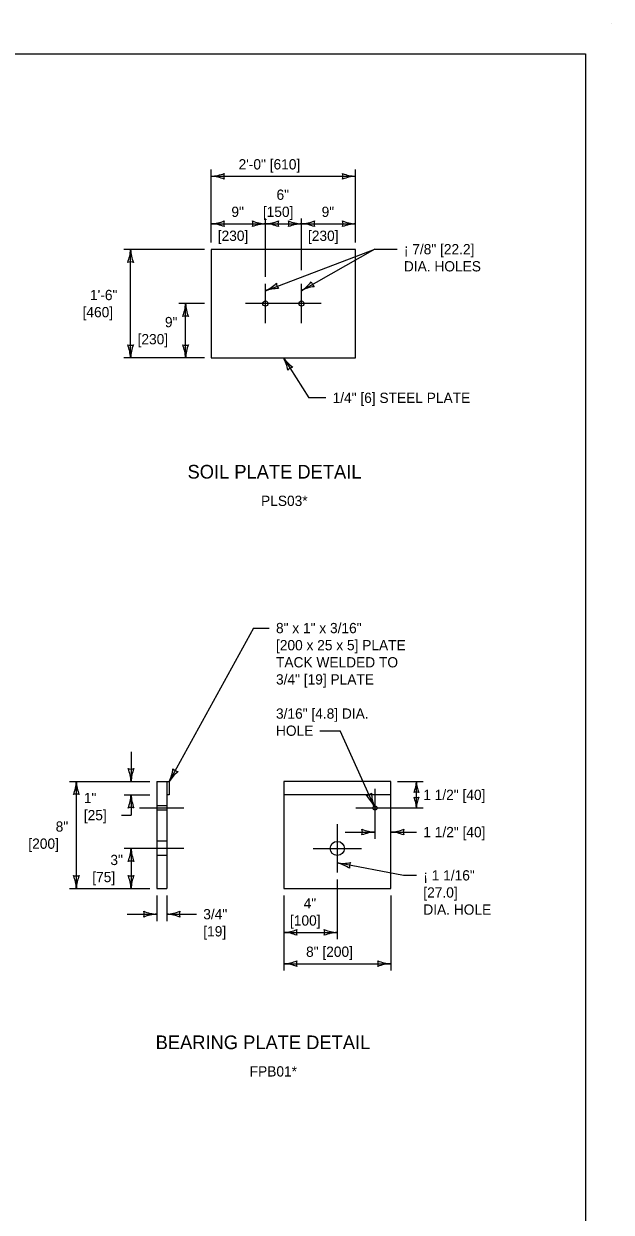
# Model space of a CAD drawing. Extents: x 49991.4 to 50021, y 49987.6 to 50011.4.
# Drawn here: x 50013.47 to 50016.9, y 49992.23 to 49999.18 of the extents above; entities that cross this region are included whole.
import ezdxf

# ---------------------------------------------------------------- set-up
doc = ezdxf.new("R2010")
doc.units = 0
for name, color, linetype in [('Level 1', 7, 'Continuous'), ('Level 2', 7, 'Continuous'), ('Level 3', 7, 'Continuous'), ('Level 4', 7, 'Continuous'), ('Level 5', 7, 'Continuous')]:
    doc.layers.add(name, color=color, linetype=linetype)

msp = doc.modelspace()

# ---------------------------------------------------------------- linework, layer by layer
at = {"layer": 'Level 1'}
for p, q in [((50016.9001, 49999.1756), (50016.9001, 49999.1756)), ((50015.406, 49997.8562), (50014.5622, 49997.8562)), ((50014.5622, 49997.8562), (50014.5622, 49997.2232)), ((50015.406, 49997.2232), (50015.406, 49997.8562)), ((50014.5622, 49997.2232), (50015.406, 49997.2232)), ((50014.2436, 49994.7447), (50014.2436, 49994.1196)), ((50014.2436, 49994.7447), (50014.3169, 49994.7447)), ((50014.3023, 49994.7447), (50014.3023, 49994.1196)), ((50014.3169, 49994.7447), (50014.3169, 49994.6666)), ((50015.6115, 49994.7447), (50014.9865, 49994.7447)), ((50014.9865, 49994.7447), (50014.9865, 49994.1196)), ((50015.6115, 49994.1196), (50015.6115, 49994.7447)), ((50014.3169, 49994.6666), (50014.3023, 49994.6666)), ((50014.2436, 49994.1196), (50014.3023, 49994.1196)), ((50014.9865, 49994.1196), (50015.6115, 49994.1196))]:
    msp.add_line(p, q, dxfattribs=at)
msp.add_lwpolyline([(49999.3835, 49998.9992), (50016.7501, 49998.9992), (50016.7501, 49987.7988), (49999.3835, 49987.7988)], close=True, dxfattribs=at)
for centre, radius in [((50014.8787, 49997.5397), 0.0154), ((50015.0896, 49997.5397), 0.0154), ((50015.2989, 49994.354), 0.0415)]:
    msp.add_circle(centre, radius, dxfattribs=at)
at = {"layer": 'Level 3'}
for p, q in [((50014.5622, 49997.8962), (50014.5622, 49998.3239)), ((50014.5622, 49998.2839), (50015.406, 49998.2839)), ((50015.406, 49997.8962), (50015.406, 49998.3239)), ((50014.5622, 49998.0062), (50014.8787, 49998.0062)), ((50014.8787, 49997.6951), (50014.8787, 49998.0374)), ((50014.8787, 49998.0062), (50015.0896, 49998.0062)), ((50015.0896, 49997.7351), (50015.0896, 49998.0374)), ((50015.0896, 49998.0062), (50015.406, 49998.0062)), ((50014.5222, 49997.8562), (50014.0507, 49997.8562)), ((50014.0907, 49997.2232), (50014.0907, 49997.8562)), ((50014.8787, 49997.6151), (50015.5181, 49997.8576)), ((50015.5181, 49997.8576), (50015.0896, 49997.6151)), ((50015.5181, 49997.8576), (50015.6483, 49997.8576)), ((50014.5222, 49997.5397), (50014.3722, 49997.5397)), ((50014.4122, 49997.2232), (50014.4122, 49997.5397)), ((50014.5222, 49997.2232), (50014.0507, 49997.2232)), ((50014.9841, 49997.2232), (50015.1329, 49996.9886)), ((50015.2316, 49996.9886), (50015.1329, 49996.9886)), ((50014.8092, 49995.6425), (50014.3169, 49994.7447)), ((50014.8092, 49995.6425), (50014.9008, 49995.6425)), ((50015.1976, 49995.0425), (50015.3153, 49995.0425)), ((50015.5142, 49994.6016), (50015.3153, 49995.0425)), ((50014.0936, 49994.9181), (50014.0936, 49994.7447)), ((50013.7337, 49994.7447), (50014.2036, 49994.7447)), ((50013.7737, 49994.7447), (50013.7737, 49994.1196)), ((50015.6515, 49994.7446), (50015.8015, 49994.7446)), ((50015.7615, 49994.5904), (50015.7615, 49994.7446)), ((50014.0536, 49994.6666), (50014.2036, 49994.6666)), ((50014.0936, 49994.6666), (50014.0936, 49994.5488)), ((50014.0373, 49994.5488), (50014.0936, 49994.5488)), ((50015.3458, 49994.4497), (50015.5193, 49994.4497)), ((50015.6115, 49994.4497), (50015.7619, 49994.4497)), ((50014.0936, 49994.354), (50014.0936, 49994.1196)), ((50015.6861, 49994.1967), (50015.2989, 49994.269)), ((50015.2989, 49994.1725), (50015.2989, 49993.8229)), ((50015.7619, 49994.1967), (50015.6861, 49994.1967)), ((50013.7337, 49994.1196), (50014.2036, 49994.1196)), ((50014.2436, 49994.0796), (50014.2436, 49993.9296)), ((50014.3023, 49994.0796), (50014.3023, 49993.9296)), ((50014.9865, 49994.0796), (50014.9865, 49993.6402)), ((50015.6115, 49994.0796), (50015.6115, 49993.6402)), ((50014.0701, 49993.9696), (50014.2436, 49993.9696)), ((50014.3023, 49993.9696), (50014.4757, 49993.9696)), ((50014.9865, 49993.8629), (50015.2989, 49993.8629)), ((50014.9865, 49993.6802), (50015.6115, 49993.6802))]:
    msp.add_line(p, q, dxfattribs=at)
msp.add_circle((50015.5193, 49994.5904), 0.0124, dxfattribs=at)
for centre, radius, start, end in [((50014.5507, 49998.5166), 0.233, 272.82731, 292.07716), ((50014.553, 49998.0617), 0.2223, 67.45601, 87.63952), ((50014.6904, 49998.2839), 0.0548, 162.13882, 197.86118), ((50015.4151, 49998.506), 0.2223, 247.45601, 267.63952), ((50015.2778, 49998.2839), 0.0548, 342.13882, 17.86118), ((50015.4175, 49998.0511), 0.233, 92.82731, 112.07716), ((50014.5507, 49998.2389), 0.233, 272.82731, 292.07716), ((50014.553, 49997.7841), 0.2223, 67.45601, 87.63952), ((50014.6904, 49998.0062), 0.0548, 162.13882, 197.86118), ((50014.8878, 49998.2283), 0.2223, 247.45601, 267.63952), ((50014.7505, 49998.0062), 0.0548, 342.13882, 17.86118), ((50014.8902, 49997.7735), 0.233, 92.82731, 112.07716), ((50014.8672, 49998.2389), 0.233, 272.82731, 292.07716), ((50014.8695, 49997.7841), 0.2223, 67.45601, 87.63952), ((50015.0069, 49998.0062), 0.0548, 162.13882, 197.86118), ((50015.0987, 49998.2283), 0.2223, 247.45601, 267.63952), ((50014.9614, 49998.0062), 0.0548, 342.13882, 17.86118), ((50015.1011, 49997.7735), 0.233, 92.82731, 112.07716), ((50015.0781, 49998.2389), 0.233, 272.82731, 292.07716), ((50015.0804, 49997.7841), 0.2223, 67.45601, 87.63952), ((50015.2178, 49998.0062), 0.0548, 162.13882, 197.86118), ((50015.4151, 49998.2283), 0.2223, 247.45601, 267.63952), ((50015.2778, 49998.0062), 0.0548, 342.13882, 17.86118), ((50015.4175, 49997.7735), 0.233, 92.82731, 112.07716), ((50013.8686, 49997.8654), 0.2223, 337.45601, 357.63952), ((50014.3234, 49997.8677), 0.233, 182.82731, 202.07716), ((50014.0907, 49997.728), 0.0548, 72.13882, 107.86118), ((50014.7836, 49997.8278), 0.233, 294.0796, 313.32945), ((50014.9982, 49997.6616), 0.0548, 183.39111, 219.11347), ((50014.9639, 49997.8113), 0.233, 302.64315, 321.893), ((50015.2008, 49997.6789), 0.0548, 191.95466, 227.67702), ((50014.9507, 49997.4048), 0.2223, 88.7083, 108.89181), ((50015.1921, 49997.4178), 0.2223, 97.27185, 117.45536), ((50014.1901, 49997.5489), 0.2223, 337.45601, 357.63952), ((50014.6449, 49997.5512), 0.233, 182.82731, 202.07716), ((50014.4122, 49997.4115), 0.0548, 72.13882, 107.86118), ((50014.0907, 49997.3514), 0.0548, 252.13882, 287.86118), ((50013.858, 49997.2117), 0.233, 2.82731, 22.07716), ((50014.3129, 49997.214), 0.2223, 157.45601, 177.63952), ((50014.4122, 49997.3514), 0.0548, 252.13882, 287.86118), ((50014.1795, 49997.2117), 0.233, 2.82731, 22.07716), ((50014.6343, 49997.214), 0.2223, 157.45601, 177.63952), ((50014.7914, 49997.1123), 0.2223, 9.72728, 29.91079), ((50015.1747, 49997.3572), 0.233, 215.09858, 234.34843), ((50015.0525, 49997.1148), 0.0548, 104.41009, 140.13245), ((50014.0936, 49994.8729), 0.0548, 252.13882, 287.86118), ((50013.8608, 49994.7332), 0.233, 2.82731, 22.07716), ((50014.3157, 49994.7355), 0.2223, 157.45601, 177.63952), ((50014.1073, 49994.8465), 0.233, 334.08756, 353.33741), ((50014.5072, 49994.6298), 0.2223, 128.71626, 148.89977), ((50014.3785, 49994.8571), 0.0548, 223.39907, 259.12143), ((50013.5516, 49994.7538), 0.2223, 337.45601, 357.63952), ((50014.0065, 49994.7562), 0.233, 182.82731, 202.07716), ((50015.5763, 49994.7522), 0.1853, 337.45601, 357.63952), ((50015.9554, 49994.7541), 0.1942, 182.82731, 202.07716), ((50013.7737, 49994.6164), 0.0548, 72.13882, 107.86118), ((50013.8714, 49994.6757), 0.2223, 337.45601, 357.63952), ((50014.3263, 49994.6781), 0.233, 182.82731, 202.07716), ((50015.4633, 49994.7193), 0.0548, 275.5221, 311.24446), ((50015.3051, 49994.4987), 0.233, 26.21059, 45.46044), ((50015.7217, 49994.6814), 0.2223, 180.83929, 201.0228), ((50015.7615, 49994.6377), 0.0456, 72.13882, 107.86118), ((50015.7615, 49994.6972), 0.0456, 252.13882, 287.86118), ((50015.5675, 49994.5808), 0.1942, 2.82731, 22.07716), ((50015.9466, 49994.5827), 0.1853, 157.45601, 177.63952), ((50014.0936, 49994.5383), 0.0548, 72.13882, 107.86118), ((50015.5284, 49994.6718), 0.2223, 247.45601, 267.63952), ((50015.391, 49994.4497), 0.0548, 342.13882, 17.86118), ((50015.5307, 49994.2169), 0.233, 92.82731, 112.07716), ((50015.6, 49994.6824), 0.233, 272.82731, 292.07716), ((50015.6023, 49994.2275), 0.2223, 67.45601, 87.63952), ((50015.7397, 49994.4497), 0.0548, 162.13882, 197.86118), ((50013.8714, 49994.3631), 0.2223, 337.45601, 357.63952), ((50014.3263, 49994.3655), 0.233, 182.82731, 202.07716), ((50014.0936, 49994.2257), 0.0548, 72.13882, 107.86118), ((50015.3305, 49994.4998), 0.233, 262.19767, 281.44752), ((50015.2489, 49994.0523), 0.2223, 56.82637, 77.00988), ((50015.4249, 49994.2453), 0.0548, 151.50918, 187.23154), ((50013.7737, 49994.2478), 0.0548, 252.13882, 287.86118), ((50013.541, 49994.1081), 0.233, 2.82731, 22.07716), ((50013.9959, 49994.1104), 0.2223, 157.45601, 177.63952), ((50014.0936, 49994.2478), 0.0548, 252.13882, 287.86118), ((50013.8608, 49994.1081), 0.233, 2.82731, 22.07716), ((50014.3157, 49994.1104), 0.2223, 157.45601, 177.63952), ((50014.2527, 49994.1917), 0.2223, 247.45601, 267.63952), ((50014.1153, 49993.9696), 0.0548, 342.13882, 17.86118), ((50014.255, 49993.7368), 0.233, 92.82731, 112.07716), ((50014.2908, 49994.2023), 0.233, 272.82731, 292.07716), ((50014.2931, 49993.7474), 0.2223, 67.45601, 87.63952), ((50014.4305, 49993.9696), 0.0548, 162.13882, 197.86118), ((50014.975, 49994.0956), 0.233, 272.82731, 292.07716), ((50014.9773, 49993.6408), 0.2223, 67.45601, 87.63952), ((50015.1147, 49993.8629), 0.0548, 162.13882, 197.86118), ((50015.308, 49994.085), 0.2223, 247.45601, 267.63952), ((50015.1706, 49993.8629), 0.0548, 342.13882, 17.86118), ((50015.3103, 49993.6302), 0.233, 92.82731, 112.07716), ((50014.975, 49993.9129), 0.233, 272.82731, 292.07716), ((50014.9773, 49993.4581), 0.2223, 67.45601, 87.63952), ((50015.1147, 49993.6802), 0.0548, 162.13882, 197.86118), ((50015.6206, 49993.9023), 0.2223, 247.45601, 267.63952), ((50015.4832, 49993.6802), 0.0548, 342.13882, 17.86118), ((50015.6229, 49993.4475), 0.233, 92.82731, 112.07716)]:
    msp.add_arc(centre, radius, start, end, dxfattribs=at)
at = {"layer": 'Level 4'}
for p, q in [((50015.6115, 49994.6666), (50014.9865, 49994.6666)), ((50014.3023, 49994.6028), (50014.2436, 49994.6028)), ((50014.3023, 49994.578), (50014.2436, 49994.578)), ((50014.3023, 49994.3956), (50014.2436, 49994.3956)), ((50014.3023, 49994.3125), (50014.2436, 49994.3125))]:
    msp.add_line(p, q, dxfattribs=at)
at = {"layer": 'Level 5'}
for p, q in [((50014.8787, 49997.4243), (50014.8787, 49997.6551)), ((50015.0896, 49997.4243), (50015.0896, 49997.6551)), ((50015.205, 49997.54), (50014.7633, 49997.54)), ((50015.5193, 49994.7028), (50015.5193, 49994.4097)), ((50014.4023, 49994.5904), (50014.1436, 49994.5904)), ((50015.8015, 49994.5904), (50015.4069, 49994.5904)), ((50015.2989, 49994.4956), (50015.2989, 49994.2125)), ((50014.4023, 49994.354), (50014.0536, 49994.354)), ((50015.1574, 49994.354), (50015.4405, 49994.354))]:
    msp.add_line(p, q, dxfattribs=at)

# ---------------------------------------------------------------- texts
at = {"layer": 'Level 2'}
for s, height, p in [('2\'-0" [610]', 0.06, (50014.722, 49998.3239)), ('6"', 0.06, (50014.9439, 49998.1462)), ('9"', 0.06, (50014.6801, 49998.0462)), ('[150]', 0.06, (50014.864, 49998.0462)), ('9"', 0.06, (50015.2074, 49998.0462)), ('[230]', 0.06, (50014.6003, 49997.9062)), ('[230]', 0.06, (50015.1277, 49997.9062)), ('¡ 7/8" [22.2]', 0.06, (50015.6883, 49997.8276)), ('DIA. HOLES', 0.06, (50015.6883, 49997.7276)), ('1\'-6"', 0.06, (50013.8538, 49997.5597)), ('[460]', 0.06, (50013.8103, 49997.4597)), ('9"', 0.06, (50014.2915, 49997.4015)), ('[230]', 0.06, (50014.1318, 49997.3015)), ('1/4" [6] STEEL PLATE', 0.06, (50015.2716, 49996.9586)), ('SOIL PLATE DETAIL', 0.08, (50014.4237, 49996.5165)), ('PLS03*', 0.06, (50014.8535, 49996.3565)), ('8" x 1" x 3/16"', 0.06, (50014.9408, 49995.6125)), ('[200 x 25 x 5] PLATE ', 0.06, (50014.9408, 49995.5125)), ('TACK WELDED TO  ', 0.06, (50014.9408, 49995.4125)), ('3/4" [19] PLATE', 0.06, (50014.9408, 49995.3125)), ('3/16" [4.8] DIA.', 0.06, (50014.9408, 49995.1125)), ('HOLE', 0.06, (50014.9408, 49995.0125)), ('1"', 0.06, (50013.8177, 49994.6188)), ('1 1/2" [40]', 0.06, (50015.8015, 49994.6375)), ('[25]', 0.06, (50013.8177, 49994.5188)), ('8"', 0.06, (50013.6531, 49994.4521)), ('1 1/2" [40]', 0.06, (50015.8019, 49994.4197)), ('[200]', 0.06, (50013.4933, 49994.3521)), ('3"', 0.06, (50013.9729, 49994.2568)), ('[75]', 0.06, (50013.867, 49994.1568)), ('¡ 1 1/16"', 0.06, (50015.8019, 49994.1667)), ('[27.0]', 0.06, (50015.8019, 49994.0667)), ('4"', 0.06, (50015.1024, 49994.0029)), ('DIA. HOLE', 0.06, (50015.8019, 49993.9667)), ('3/4"', 0.06, (50014.5157, 49993.9396)), ('[100]', 0.06, (50015.0226, 49993.9029)), ('[19]', 0.06, (50014.5157, 49993.8396)), ('8" [200]', 0.06, (50015.1165, 49993.7202)), ('BEARING PLATE DETAIL', 0.08, (50014.2374, 49993.1805)), ('FPB01*', 0.06, (50014.7871, 49993.0205))]:
    msp.add_text(s, height=height, dxfattribs=at).set_placement(p)

doc.saveas('drawing.dxf')
